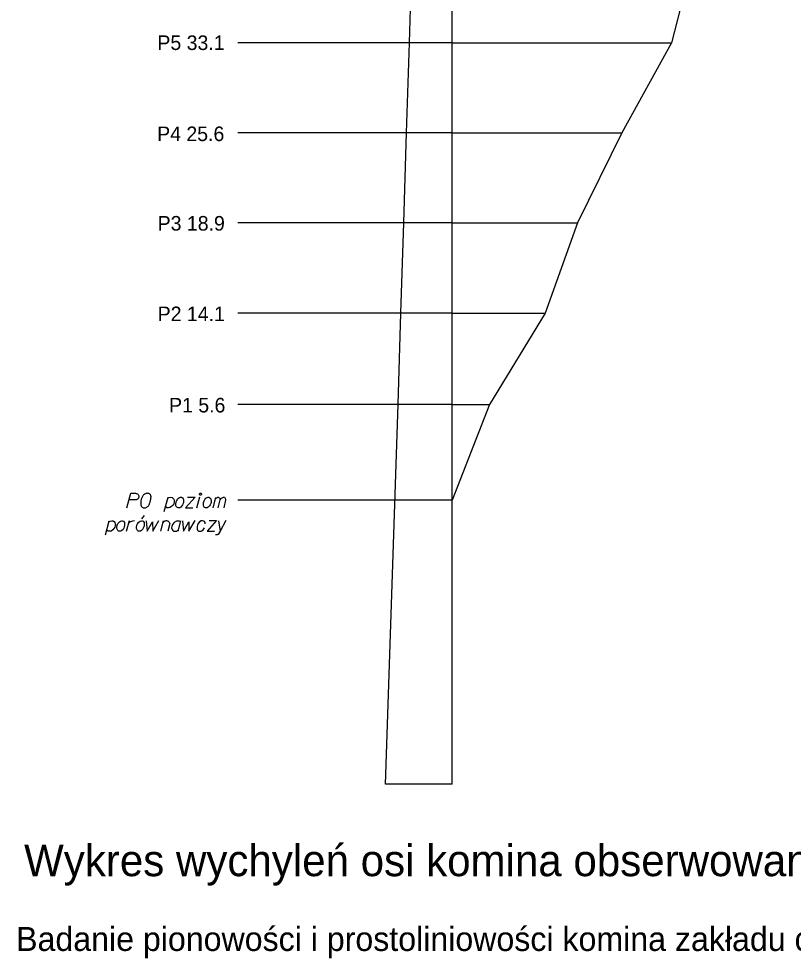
# Model space of a CAD drawing. Extents: x 138 to 264, y -75 to 121.
# Drawn here: x 170.72 to 182.42, y 85.34 to 99.52 of the extents above; entities that cross this region are included whole.
import ezdxf

# ---------------------------------------------------------------- set-up
doc = ezdxf.new("R2010")
doc.units = 0
for name, color, linetype in [('Opisy', 7, 'Continuous'), ('Standart wykresów', 7, 'Continuous'), ('Wykresy 4 maj 2008', 7, 'Continuous')]:
    doc.layers.add(name, color=color, linetype=linetype)

msp = doc.modelspace()

# ---------------------------------------------------------------- linework, layer by layer
at = {"layer": 'Standart wykresów'}
for p, q in [((177.265, 87.967), (177.265, 108.051)), ((176.618, 99.158), (176.663, 100.549)), ((177.265, 99.158), (174.028, 99.158)), ((176.576, 97.799), (176.618, 99.158)), ((177.265, 97.799), (174.028, 97.799)), ((176.534, 96.441), (176.576, 97.799)), ((177.265, 96.441), (174.028, 96.441)), ((176.491, 95.074), (176.534, 96.441)), ((177.265, 95.074), (174.028, 95.074)), ((176.447, 93.698), (176.491, 95.074)), ((177.265, 93.698), (174.028, 93.698)), ((176.259, 87.967), (176.447, 93.698)), ((177.265, 92.253), (174.028, 92.253)), ((177.265, 87.967), (176.259, 87.967))]:
    msp.add_line(p, q, dxfattribs=at)
for points in [[(172.349, 92.137), (172.408, 92.357), (172.483, 92.357), (172.493, 92.355), (172.498, 92.354), (172.509, 92.348), (172.515, 92.343), (172.521, 92.336), (172.526, 92.328), (172.529, 92.316), (172.531, 92.305), (172.529, 92.296), (172.528, 92.29), (172.524, 92.283), (172.521, 92.277), (172.515, 92.271), (172.509, 92.265), (172.503, 92.262), (172.495, 92.258), (172.486, 92.257), (172.382, 92.257)], [(172.664, 92.357), (172.661, 92.357), (172.651, 92.355), (172.644, 92.354), (172.638, 92.352), (172.63, 92.348), (172.619, 92.343), (172.611, 92.338), (172.602, 92.331), (172.597, 92.324), (172.592, 92.316), (172.587, 92.307), (172.581, 92.296), (172.578, 92.29), (172.574, 92.279), (172.569, 92.262), (172.564, 92.236), (172.561, 92.215), (172.561, 92.196), (172.562, 92.182), (172.569, 92.167), (172.574, 92.158), (172.583, 92.148), (172.593, 92.141), (172.599, 92.139), (172.609, 92.137), (172.618, 92.137), (172.632, 92.139), (172.644, 92.142), (172.652, 92.148), (172.664, 92.156), (172.67, 92.161), (172.677, 92.168), (172.682, 92.175), (172.685, 92.18), (172.689, 92.189), (172.69, 92.193), (172.694, 92.201), (172.697, 92.212), (172.701, 92.222), (172.703, 92.229), (172.704, 92.234), (172.706, 92.241), (172.709, 92.257), (172.711, 92.265), (172.713, 92.274), (172.715, 92.286), (172.716, 92.302), (172.716, 92.307), (172.715, 92.314), (172.713, 92.321), (172.708, 92.331), (172.703, 92.338), (172.697, 92.343), (172.69, 92.348), (172.684, 92.352), (172.678, 92.354), (172.673, 92.355), (172.664, 92.357)], [(173.458, 92.357), (173.466, 92.357), (173.472, 92.354), (173.477, 92.347), (173.477, 92.338), (173.472, 92.331), (173.466, 92.328), (173.458, 92.328), (173.453, 92.331), (173.447, 92.338), (173.447, 92.347), (173.453, 92.354), (173.458, 92.357)], [(172.916, 92.08), (172.974, 92.296)], [(172.969, 92.277), (172.987, 92.291), (173.013, 92.296), (173.033, 92.293), (173.047, 92.283), (173.058, 92.269), (173.065, 92.25), (173.066, 92.232), (173.063, 92.217), (173.058, 92.198), (173.044, 92.177), (173.026, 92.158), (173, 92.141), (172.978, 92.137), (172.957, 92.139), (172.935, 92.151)], [(173.163, 92.296), (173.175, 92.296), (173.189, 92.29), (173.203, 92.271), (173.205, 92.262), (173.207, 92.253), (173.207, 92.246), (173.207, 92.22), (173.201, 92.203), (173.193, 92.182), (173.182, 92.165), (173.165, 92.149), (173.149, 92.137), (173.123, 92.137), (173.113, 92.141), (173.103, 92.149), (173.097, 92.158), (173.091, 92.179), (173.091, 92.21), (173.094, 92.22), (173.101, 92.243), (173.108, 92.255), (173.111, 92.262), (173.129, 92.281), (173.146, 92.291), (173.163, 92.296)], [(173.267, 92.3), (173.38, 92.3), (173.236, 92.137), (173.347, 92.137)], [(173.409, 92.137), (173.454, 92.305)], [(173.579, 92.296), (173.591, 92.296), (173.605, 92.29), (173.619, 92.271), (173.621, 92.262), (173.622, 92.253), (173.622, 92.246), (173.622, 92.22), (173.617, 92.203), (173.608, 92.182), (173.598, 92.165), (173.581, 92.149), (173.565, 92.137), (173.539, 92.137), (173.529, 92.141), (173.518, 92.149), (173.513, 92.158), (173.506, 92.179), (173.506, 92.21), (173.51, 92.22), (173.517, 92.243), (173.524, 92.255), (173.527, 92.262), (173.544, 92.281), (173.562, 92.291), (173.579, 92.296)], [(173.652, 92.137), (173.692, 92.295)], [(173.681, 92.253), (173.69, 92.272), (173.699, 92.283), (173.709, 92.29), (173.719, 92.295), (173.726, 92.298), (173.737, 92.298), (173.74, 92.296), (173.747, 92.29), (173.754, 92.281), (173.759, 92.265), (173.761, 92.257), (173.77, 92.272), (173.78, 92.283), (173.79, 92.29), (173.801, 92.295), (173.809, 92.298), (173.818, 92.298), (173.825, 92.296), (173.83, 92.29), (173.835, 92.281), (173.841, 92.265), (173.842, 92.257), (173.813, 92.137)], [(173.731, 92.137), (173.761, 92.257)], [(172.026, 91.727), (172.085, 91.943)], [(172.08, 91.924), (172.097, 91.938), (172.123, 91.943), (172.144, 91.94), (172.158, 91.929), (172.168, 91.916), (172.175, 91.897), (172.177, 91.879), (172.173, 91.864), (172.168, 91.845), (172.154, 91.824), (172.137, 91.805), (172.111, 91.787), (172.088, 91.784), (172.068, 91.786), (172.045, 91.798)], [(172.274, 91.943), (172.286, 91.943), (172.3, 91.936), (172.314, 91.917), (172.315, 91.909), (172.317, 91.9), (172.317, 91.893), (172.317, 91.867), (172.312, 91.85), (172.303, 91.829), (172.293, 91.812), (172.275, 91.796), (172.26, 91.784), (172.234, 91.784), (172.223, 91.787), (172.213, 91.796), (172.208, 91.805), (172.201, 91.825), (172.201, 91.857), (172.204, 91.867), (172.211, 91.89), (172.218, 91.902), (172.222, 91.909), (172.239, 91.928), (172.256, 91.938), (172.274, 91.943)], [(172.346, 91.784), (172.39, 91.948)], [(172.379, 91.909), (172.388, 91.916), (172.407, 91.929), (172.428, 91.938), (172.443, 91.943), (172.468, 91.948)], [(172.57, 91.943), (172.582, 91.943), (172.596, 91.936), (172.61, 91.917), (172.611, 91.909), (172.613, 91.9), (172.613, 91.893), (172.613, 91.867), (172.608, 91.85), (172.599, 91.829), (172.589, 91.812), (172.572, 91.796), (172.556, 91.784), (172.53, 91.784), (172.52, 91.787), (172.509, 91.796), (172.504, 91.805), (172.497, 91.825), (172.497, 91.857), (172.501, 91.867), (172.508, 91.89), (172.514, 91.902), (172.518, 91.909), (172.535, 91.928), (172.553, 91.938), (172.57, 91.943)], [(172.613, 92.02), (172.57, 91.971)], [(172.643, 91.942), (172.656, 91.784), (172.74, 91.928), (172.741, 91.784), (172.833, 91.945)], [(172.863, 91.784), (172.906, 91.943)], [(172.896, 91.905), (172.901, 91.914), (172.908, 91.924), (172.913, 91.929), (172.92, 91.936), (172.927, 91.94), (172.935, 91.943), (172.944, 91.945), (172.951, 91.945), (172.96, 91.943), (172.967, 91.94), (172.973, 91.936), (172.98, 91.931), (172.987, 91.924), (172.991, 91.919), (172.994, 91.912), (172.998, 91.903), (172.967, 91.784)], [(173.157, 91.929), (173.145, 91.938), (173.116, 91.938), (173.098, 91.935), (173.067, 91.917), (173.041, 91.886), (173.029, 91.853), (173.027, 91.836), (173.029, 91.822), (173.034, 91.81), (173.044, 91.796), (173.057, 91.787), (173.076, 91.784), (173.09, 91.786), (173.103, 91.787), (173.122, 91.798)], [(173.161, 91.943), (173.119, 91.784)], [(173.19, 91.942), (173.204, 91.784), (173.287, 91.928), (173.289, 91.784), (173.381, 91.945)], [(173.533, 91.897), (173.531, 91.917), (173.523, 91.931), (173.512, 91.938), (173.491, 91.942), (173.472, 91.942), (173.448, 91.926), (173.429, 91.9), (173.415, 91.874), (173.41, 91.855), (173.41, 91.825), (173.412, 91.815), (173.419, 91.801), (173.434, 91.787), (173.452, 91.784), (173.471, 91.786), (173.481, 91.789), (173.504, 91.805), (173.521, 91.834)], [(173.594, 91.947), (173.706, 91.947), (173.562, 91.784), (173.673, 91.784)], [(173.846, 91.945), (173.758, 91.784), (173.73, 91.737), (173.723, 91.734), (173.715, 91.73), (173.698, 91.727), (173.691, 91.727)], [(173.736, 91.943), (173.758, 91.784)]]:
    msp.add_lwpolyline(points, dxfattribs=at)
at = {"layer": 'Wykresy 4 maj 2008'}
for p, q in [((177.265, 99.158), (180.575, 99.158)), ((177.265, 97.799), (179.826, 97.799)), ((177.265, 96.441), (179.155, 96.441)), ((177.265, 95.074), (178.671, 95.074)), ((177.265, 93.698), (177.827, 93.698))]:
    msp.add_line(p, q, dxfattribs=at)
msp.add_lwpolyline([(181.391, 107.967), (180.42, 107.711), (181.165, 107.348), (181.798, 106.65), (180.986, 106.463), (182.227, 105.937), (181.841, 105.369), (181.902, 104.901), (181.745, 104.384), (182.072, 103.925), (181.698, 102.945), (181.822, 101.951), (180.933, 100.549), (180.575, 99.158), (179.826, 97.799), (179.155, 96.441), (178.671, 95.074), (177.827, 93.698), (177.265, 92.253)], dxfattribs=at)

# ---------------------------------------------------------------- texts
at = {"layer": 'Opisy'}
for s, height, p in [('Wykres wychyleń osi komina obserwowanych ze stanowiska 1000', 0.47516, (170.798, 86.577)), ('Badanie pionowości i prostoliniowości komina zakładu ceramicznego "Ceramika Stróże"', 0.36281, (170.678, 85.448))]:
    msp.add_text(s, height=height, dxfattribs=at).set_placement(p)
at = {"layer": 'Wykresy 4 maj 2008'}
for s, p in [('P5 33.1', (172.812, 99.048)), ('P4 25.6', (172.808, 97.673)), ('P3 18.9', (172.816, 96.322)), ('P2 14.1', (172.816, 94.955)), ('P1 5.6', (172.988, 93.577))]:
    msp.add_text(s, height=0.22, dxfattribs=at).set_placement(p)

doc.saveas('drawing.dxf')
